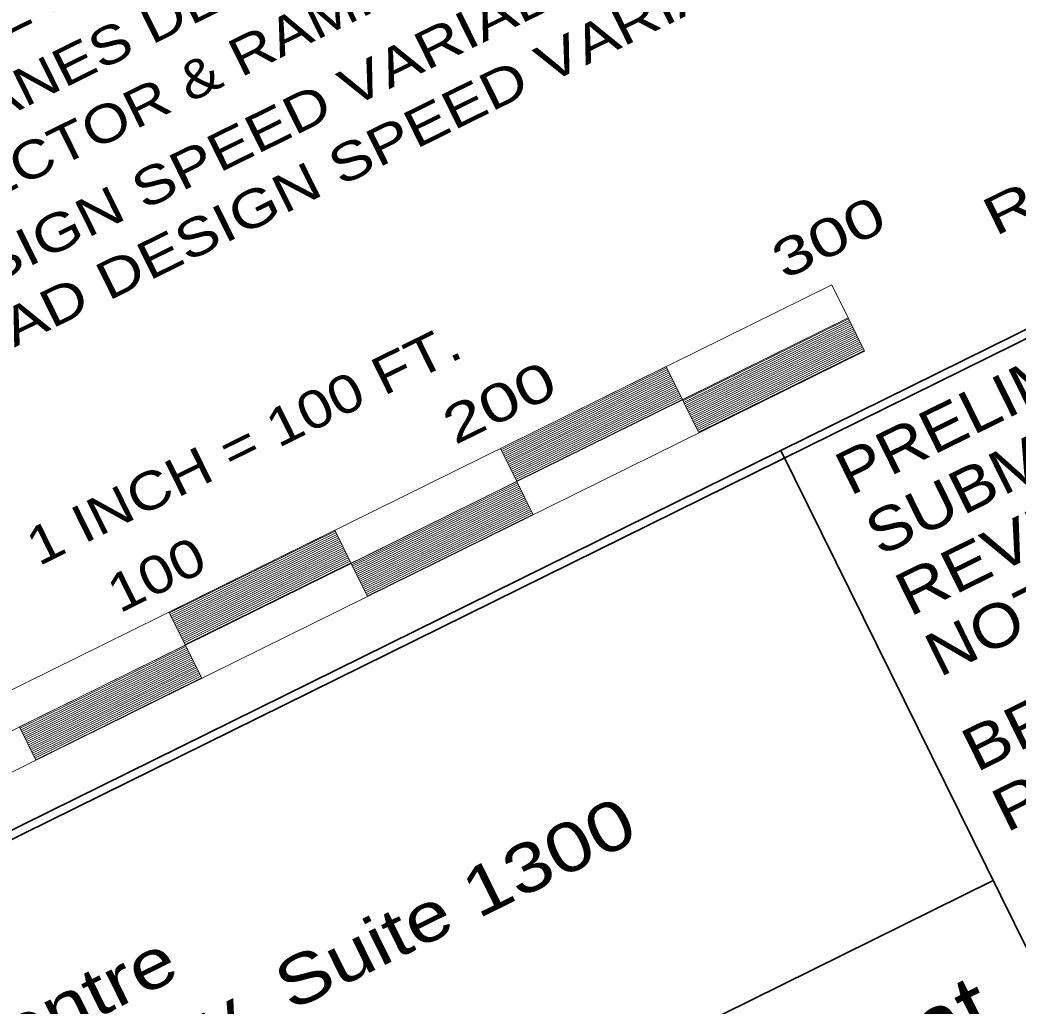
# Model space of a CAD drawing. Extents: x 2356606 to 2371222, y 6973096 to 6982644.
# Drawn here: x 2370337.8 to 2370607.9, y 6979398.7 to 6979665.5 of the extents above; entities that cross this region are included whole.
import ezdxf
from ezdxf.enums import TextEntityAlignment as Align

# ---------------------------------------------------------------- set-up
doc = ezdxf.new("R2010")
doc.units = 0
doc.header["$LTSCALE"] = 2
doc.layers.add('62', color=7, linetype='Continuous', lineweight=13)
doc.layers.add('63', color=7, linetype='Continuous', lineweight=13)

msp = doc.modelspace()

# ---------------------------------------------------------------- linework, layer by layer
at = {"layer": '62', "lineweight": 35}
for p, q in [((2370772.563, 6979661.979), (2370188.769, 6979373.856)), ((2370641.531, 6979350.877), (2370543.728, 6979549.041)), ((2370601.161, 6979432.671), (2370246.201, 6979257.487))]:
    msp.add_line(p, q, dxfattribs=at)
at = {"layer": '62'}
for p, q in [((2370198.776, 6979416.806), (2370557.503, 6979593.85)), ((2370557.503, 6979593.85), (2370561.929, 6979584.882)), ((2370203.203, 6979407.838), (2370561.929, 6979584.882)), ((2370517.206, 6979562.512), (2370562.047, 6979584.641)), ((2370517.428, 6979562.063), (2370562.268, 6979584.193)), ((2370517.648, 6979561.614), (2370562.49, 6979583.745)), ((2370517.869, 6979561.166), (2370562.711, 6979583.296)), ((2370518.09, 6979560.719), (2370562.932, 6979582.848)), ((2370561.929, 6979584.882), (2370566.356, 6979575.913)), ((2370518.312, 6979560.269), (2370563.153, 6979582.4)), ((2370518.533, 6979559.821), (2370563.374, 6979581.952)), ((2370518.755, 6979559.373), (2370563.596, 6979581.505)), ((2370518.977, 6979558.925), (2370563.817, 6979581.055)), ((2370519.198, 6979558.476), (2370564.038, 6979580.607)), ((2370519.419, 6979558.028), (2370564.261, 6979580.159)), ((2370519.641, 6979557.58), (2370564.482, 6979579.71)), ((2370519.86, 6979557.13), (2370564.703, 6979579.262)), ((2370520.082, 6979556.682), (2370564.923, 6979578.813)), ((2370520.304, 6979556.233), (2370565.145, 6979578.365)), ((2370520.525, 6979555.785), (2370565.366, 6979577.915)), ((2370520.747, 6979555.336), (2370565.588, 6979577.467)), ((2370520.968, 6979554.888), (2370565.81, 6979577.019)), ((2370521.19, 6979554.44), (2370566.03, 6979576.57)), ((2370521.411, 6979553.992), (2370566.253, 6979576.122)), ((2370512.661, 6979571.719), (2370517.087, 6979562.751)), ((2370467.995, 6979549.238), (2370512.834, 6979571.368)), ((2370468.217, 6979548.789), (2370513.057, 6979570.919)), ((2370468.438, 6979548.341), (2370513.277, 6979570.471)), ((2370468.658, 6979547.893), (2370513.499, 6979570.023)), ((2370468.879, 6979547.444), (2370513.72, 6979569.573)), ((2370469.101, 6979546.995), (2370513.941, 6979569.125)), ((2370469.323, 6979546.547), (2370514.163, 6979568.677)), ((2370469.543, 6979546.098), (2370514.384, 6979568.229)), ((2370469.765, 6979545.65), (2370514.605, 6979567.78)), ((2370469.987, 6979545.202), (2370514.827, 6979567.331)), ((2370470.207, 6979544.753), (2370515.049, 6979566.883)), ((2370470.429, 6979544.305), (2370515.27, 6979566.436)), ((2370470.65, 6979543.857), (2370515.49, 6979565.987)), ((2370470.872, 6979543.409), (2370515.711, 6979565.539)), ((2370471.092, 6979542.96), (2370515.933, 6979565.09)), ((2370471.314, 6979542.512), (2370516.155, 6979564.642)), ((2370471.536, 6979542.064), (2370516.376, 6979564.195)), ((2370471.756, 6979541.615), (2370516.597, 6979563.745)), ((2370471.978, 6979541.167), (2370516.819, 6979563.297)), ((2370472.2, 6979540.719), (2370517.039, 6979562.848)), ((2370517.087, 6979562.751), (2370521.514, 6979553.782)), ((2370467.822, 6979549.589), (2370472.248, 6979540.621)), ((2370427.579, 6979518.139), (2370472.419, 6979540.269)), ((2370427.801, 6979517.691), (2370472.641, 6979539.821)), ((2370428.021, 6979517.242), (2370472.863, 6979539.373)), ((2370472.248, 6979540.621), (2370476.673, 6979531.653)), ((2370428.243, 6979516.794), (2370473.085, 6979538.925)), ((2370428.465, 6979516.346), (2370473.305, 6979538.476)), ((2370428.685, 6979515.897), (2370473.526, 6979538.029)), ((2370428.907, 6979515.449), (2370473.748, 6979537.581)), ((2370429.128, 6979515.001), (2370473.969, 6979537.132)), ((2370429.349, 6979514.552), (2370474.191, 6979536.684)), ((2370429.571, 6979514.104), (2370474.412, 6979536.234)), ((2370429.792, 6979513.655), (2370474.633, 6979535.787)), ((2370430.014, 6979513.207), (2370474.855, 6979535.339)), ((2370430.235, 6979512.758), (2370475.076, 6979534.889)), ((2370430.457, 6979512.309), (2370475.298, 6979534.44)), ((2370430.677, 6979511.861), (2370475.519, 6979533.992)), ((2370430.899, 6979511.413), (2370475.74, 6979533.543)), ((2370431.12, 6979510.964), (2370475.961, 6979533.096)), ((2370431.341, 6979510.516), (2370476.182, 6979532.647)), ((2370431.563, 6979510.068), (2370476.405, 6979532.199)), ((2370431.784, 6979509.621), (2370476.625, 6979531.75)), ((2370378.269, 6979505.067), (2370423.108, 6979527.197)), ((2370378.49, 6979504.619), (2370423.33, 6979526.749)), ((2370378.712, 6979504.17), (2370423.552, 6979526.301)), ((2370378.933, 6979503.72), (2370423.773, 6979525.851)), ((2370422.981, 6979527.458), (2370427.406, 6979518.49)), ((2370379.154, 6979503.272), (2370423.995, 6979525.403)), ((2370379.375, 6979502.824), (2370424.215, 6979524.954)), ((2370379.596, 6979502.376), (2370424.437, 6979524.506)), ((2370379.818, 6979501.929), (2370424.657, 6979524.058)), ((2370380.039, 6979501.479), (2370424.879, 6979523.609)), ((2370380.261, 6979501.031), (2370425.101, 6979523.161)), ((2370380.482, 6979500.584), (2370425.322, 6979522.712)), ((2370380.702, 6979500.135), (2370425.544, 6979522.264)), ((2370380.924, 6979499.686), (2370425.765, 6979521.816)), ((2370381.145, 6979499.237), (2370425.986, 6979521.367)), ((2370381.367, 6979498.789), (2370426.208, 6979520.919)), ((2370381.588, 6979498.342), (2370426.428, 6979520.471)), ((2370381.809, 6979497.892), (2370426.649, 6979520.022)), ((2370382.031, 6979497.444), (2370426.871, 6979519.574)), ((2370382.252, 6979496.995), (2370427.092, 6979519.125)), ((2370382.474, 6979496.547), (2370427.314, 6979518.678)), ((2370427.406, 6979518.49), (2370431.832, 6979509.521)), ((2370378.139, 6979505.328), (2370382.566, 6979496.36)), ((2370382.566, 6979496.36), (2370386.992, 6979487.391)), ((2370337.896, 6979473.882), (2370382.737, 6979496.012)), ((2370338.117, 6979473.435), (2370382.958, 6979495.564)), ((2370338.338, 6979472.985), (2370383.18, 6979495.115)), ((2370338.559, 6979472.538), (2370383.401, 6979494.667)), ((2370338.781, 6979472.088), (2370383.623, 6979494.219)), ((2370339.002, 6979471.64), (2370383.845, 6979493.77)), ((2370339.223, 6979471.193), (2370384.064, 6979493.323)), ((2370339.445, 6979470.744), (2370384.286, 6979492.874)), ((2370339.667, 6979470.295), (2370384.507, 6979492.426)), ((2370339.887, 6979469.847), (2370384.729, 6979491.979)), ((2370340.109, 6979469.399), (2370384.951, 6979491.529)), ((2370340.329, 6979468.951), (2370385.171, 6979491.082)), ((2370340.551, 6979468.501), (2370385.392, 6979490.632)), ((2370340.773, 6979468.052), (2370385.613, 6979490.184)), ((2370340.994, 6979467.604), (2370385.836, 6979489.736)), ((2370341.215, 6979467.155), (2370386.056, 6979489.286)), ((2370341.437, 6979466.707), (2370386.277, 6979488.839)), ((2370341.659, 6979466.258), (2370386.499, 6979488.389)), ((2370341.88, 6979465.811), (2370386.72, 6979487.941)), ((2370342.101, 6979465.362), (2370386.943, 6979487.493)), ((2370337.726, 6979474.228), (2370342.15, 6979465.261))]:
    msp.add_line(p, q, dxfattribs=at)
for points in [[(2370521.514, 6979553.782), (2370566.356, 6979575.913), (2370561.929, 6979584.882), (2370517.087, 6979562.751)], [(2370472.248, 6979540.621), (2370517.087, 6979562.751), (2370512.661, 6979571.719), (2370467.822, 6979549.589)], [(2370431.832, 6979509.521), (2370476.673, 6979531.653), (2370472.248, 6979540.621), (2370427.406, 6979518.49)], [(2370382.566, 6979496.36), (2370427.406, 6979518.49), (2370422.981, 6979527.458), (2370378.139, 6979505.328)], [(2370342.15, 6979465.261), (2370386.992, 6979487.391), (2370382.566, 6979496.36), (2370337.726, 6979474.228)]]:
    msp.add_lwpolyline(points, close=True, dxfattribs=at)
at = {"layer": '63', "lineweight": 35}
msp.add_line((2370771.897, 6979659.152), (2370188.104, 6979371.029), dxfattribs=at)
at = {"layer": '63'}
for p, q in [((2370198.776, 6979416.806), (2370557.503, 6979593.85)), ((2370557.503, 6979593.85), (2370561.929, 6979584.882)), ((2370203.203, 6979407.838), (2370561.929, 6979584.882)), ((2370517.206, 6979562.512), (2370562.047, 6979584.641)), ((2370517.428, 6979562.063), (2370562.268, 6979584.193)), ((2370517.648, 6979561.614), (2370562.49, 6979583.745)), ((2370517.869, 6979561.166), (2370562.711, 6979583.296)), ((2370518.09, 6979560.719), (2370562.932, 6979582.848)), ((2370561.929, 6979584.882), (2370566.356, 6979575.913)), ((2370518.312, 6979560.269), (2370563.153, 6979582.4)), ((2370518.533, 6979559.821), (2370563.374, 6979581.952)), ((2370518.755, 6979559.373), (2370563.596, 6979581.505)), ((2370518.977, 6979558.925), (2370563.817, 6979581.055)), ((2370519.198, 6979558.476), (2370564.038, 6979580.607)), ((2370519.419, 6979558.028), (2370564.261, 6979580.159)), ((2370519.641, 6979557.58), (2370564.482, 6979579.71)), ((2370519.86, 6979557.13), (2370564.703, 6979579.262)), ((2370520.082, 6979556.682), (2370564.923, 6979578.813)), ((2370520.304, 6979556.233), (2370565.145, 6979578.365)), ((2370520.525, 6979555.785), (2370565.366, 6979577.915)), ((2370520.747, 6979555.336), (2370565.588, 6979577.467)), ((2370207.628, 6979398.87), (2370566.356, 6979575.913)), ((2370520.968, 6979554.888), (2370565.81, 6979577.019)), ((2370521.19, 6979554.44), (2370566.03, 6979576.57)), ((2370521.411, 6979553.992), (2370566.253, 6979576.122)), ((2370512.661, 6979571.719), (2370517.087, 6979562.751)), ((2370467.995, 6979549.238), (2370512.834, 6979571.368)), ((2370468.217, 6979548.789), (2370513.057, 6979570.919)), ((2370468.438, 6979548.341), (2370513.277, 6979570.471)), ((2370468.658, 6979547.893), (2370513.499, 6979570.023)), ((2370468.879, 6979547.444), (2370513.72, 6979569.573)), ((2370469.101, 6979546.995), (2370513.941, 6979569.125)), ((2370469.323, 6979546.547), (2370514.163, 6979568.677)), ((2370469.543, 6979546.098), (2370514.384, 6979568.229)), ((2370469.765, 6979545.65), (2370514.605, 6979567.78)), ((2370469.987, 6979545.202), (2370514.827, 6979567.331)), ((2370470.207, 6979544.753), (2370515.049, 6979566.883)), ((2370470.429, 6979544.305), (2370515.27, 6979566.436)), ((2370470.65, 6979543.857), (2370515.49, 6979565.987)), ((2370470.872, 6979543.409), (2370515.711, 6979565.539)), ((2370471.092, 6979542.96), (2370515.933, 6979565.09)), ((2370471.314, 6979542.512), (2370516.155, 6979564.642)), ((2370471.536, 6979542.064), (2370516.376, 6979564.195)), ((2370471.756, 6979541.615), (2370516.597, 6979563.745)), ((2370471.978, 6979541.167), (2370516.819, 6979563.297)), ((2370472.2, 6979540.719), (2370517.039, 6979562.848)), ((2370517.087, 6979562.751), (2370521.514, 6979553.782)), ((2370467.822, 6979549.589), (2370472.248, 6979540.621)), ((2370427.579, 6979518.139), (2370472.419, 6979540.269)), ((2370427.801, 6979517.691), (2370472.641, 6979539.821)), ((2370428.021, 6979517.242), (2370472.863, 6979539.373)), ((2370472.248, 6979540.621), (2370476.673, 6979531.653)), ((2370428.243, 6979516.794), (2370473.085, 6979538.925)), ((2370428.465, 6979516.346), (2370473.305, 6979538.476)), ((2370428.685, 6979515.897), (2370473.526, 6979538.029)), ((2370428.907, 6979515.449), (2370473.748, 6979537.581)), ((2370429.128, 6979515.001), (2370473.969, 6979537.132)), ((2370429.349, 6979514.552), (2370474.191, 6979536.684)), ((2370429.571, 6979514.104), (2370474.412, 6979536.234)), ((2370429.792, 6979513.655), (2370474.633, 6979535.787)), ((2370430.014, 6979513.207), (2370474.855, 6979535.339)), ((2370430.235, 6979512.758), (2370475.076, 6979534.889)), ((2370430.457, 6979512.309), (2370475.298, 6979534.44)), ((2370430.677, 6979511.861), (2370475.519, 6979533.992)), ((2370430.899, 6979511.413), (2370475.74, 6979533.543)), ((2370431.12, 6979510.964), (2370475.961, 6979533.096)), ((2370431.341, 6979510.516), (2370476.182, 6979532.647)), ((2370431.563, 6979510.068), (2370476.405, 6979532.199)), ((2370431.784, 6979509.621), (2370476.625, 6979531.75)), ((2370378.269, 6979505.067), (2370423.108, 6979527.197)), ((2370378.49, 6979504.619), (2370423.33, 6979526.749)), ((2370378.712, 6979504.17), (2370423.552, 6979526.301)), ((2370378.933, 6979503.72), (2370423.773, 6979525.851)), ((2370422.981, 6979527.458), (2370427.406, 6979518.49)), ((2370379.154, 6979503.272), (2370423.995, 6979525.403)), ((2370379.375, 6979502.824), (2370424.215, 6979524.954)), ((2370379.596, 6979502.376), (2370424.437, 6979524.506)), ((2370379.818, 6979501.929), (2370424.657, 6979524.058)), ((2370380.039, 6979501.479), (2370424.879, 6979523.609)), ((2370380.261, 6979501.031), (2370425.101, 6979523.161)), ((2370380.482, 6979500.584), (2370425.322, 6979522.712)), ((2370380.702, 6979500.135), (2370425.544, 6979522.264)), ((2370380.924, 6979499.686), (2370425.765, 6979521.816)), ((2370381.145, 6979499.237), (2370425.986, 6979521.367)), ((2370381.367, 6979498.789), (2370426.208, 6979520.919)), ((2370381.588, 6979498.342), (2370426.428, 6979520.471)), ((2370381.809, 6979497.892), (2370426.649, 6979520.022)), ((2370382.031, 6979497.444), (2370426.871, 6979519.574)), ((2370382.252, 6979496.995), (2370427.092, 6979519.125)), ((2370382.474, 6979496.547), (2370427.314, 6979518.678)), ((2370427.406, 6979518.49), (2370431.832, 6979509.521)), ((2370378.139, 6979505.328), (2370382.566, 6979496.36)), ((2370382.566, 6979496.36), (2370386.992, 6979487.391)), ((2370337.896, 6979473.882), (2370382.737, 6979496.012)), ((2370338.117, 6979473.435), (2370382.958, 6979495.564)), ((2370338.338, 6979472.985), (2370383.18, 6979495.115)), ((2370338.559, 6979472.538), (2370383.401, 6979494.667)), ((2370338.781, 6979472.088), (2370383.623, 6979494.219)), ((2370339.002, 6979471.64), (2370383.845, 6979493.77)), ((2370339.223, 6979471.193), (2370384.064, 6979493.323)), ((2370339.445, 6979470.744), (2370384.286, 6979492.874)), ((2370339.667, 6979470.295), (2370384.507, 6979492.426)), ((2370339.887, 6979469.847), (2370384.729, 6979491.979)), ((2370340.109, 6979469.399), (2370384.951, 6979491.529)), ((2370340.329, 6979468.951), (2370385.171, 6979491.082)), ((2370340.551, 6979468.501), (2370385.392, 6979490.632)), ((2370340.773, 6979468.052), (2370385.613, 6979490.184)), ((2370340.994, 6979467.604), (2370385.836, 6979489.736)), ((2370341.215, 6979467.155), (2370386.056, 6979489.286)), ((2370341.437, 6979466.707), (2370386.277, 6979488.839)), ((2370341.659, 6979466.258), (2370386.499, 6979488.389)), ((2370341.88, 6979465.811), (2370386.72, 6979487.941)), ((2370342.101, 6979465.362), (2370386.943, 6979487.493)), ((2370337.726, 6979474.228), (2370342.15, 6979465.261))]:
    msp.add_line(p, q, dxfattribs=at)
for points in [[(2370521.514, 6979553.782), (2370566.356, 6979575.913), (2370561.929, 6979584.882), (2370517.087, 6979562.751)], [(2370472.248, 6979540.621), (2370517.087, 6979562.751), (2370512.661, 6979571.719), (2370467.822, 6979549.589)], [(2370431.832, 6979509.521), (2370476.673, 6979531.653), (2370472.248, 6979540.621), (2370427.406, 6979518.49)], [(2370382.566, 6979496.36), (2370427.406, 6979518.49), (2370422.981, 6979527.458), (2370378.139, 6979505.328)], [(2370342.15, 6979465.261), (2370386.992, 6979487.391), (2370382.566, 6979496.36), (2370337.726, 6979474.228)]]:
    msp.add_lwpolyline(points, close=True, dxfattribs=at)

# ---------------------------------------------------------------- texts
at = {"layer": '62'}
for s, height, width, p in [('DIRECT CONNECTOR & RAMP DESIGN SPEED = 50 MPH', 10.2, 1.2, (2370425.126, 6979663.505)), ('MAIN LANES DESIGN SPEED = 60 MPH', 10.2, 1.2, (2370416.906, 6979680.165)), ('FRONTAGE ROAD DESIGN SPEED VARIABLE 35 TO 40 MPH', 10.2, 1.25, (2370442.894, 6979629.485)), ('RAMP DESIGN SPEED VARIABLE 40 TO 50 MPH', 10.2, 1.25, (2370434.232, 6979645.054)), ('ROLL 3 OF 4', 10.2, 1.4, (2370652.643, 6979632.005)), ('300', 10.2, 1.4, (2370558.899, 6979602.167)), ('SCALE:  1 INCH = 100 FT.', 10.2, 1.2, (2370370.377, 6979531.207)), ('200', 10.2, 1.4, (2370469.795, 6979557.467)), ('100', 10.2, 1.2, (2370376.975, 6979510.919)), ('Texas Department', 18.76, 1.1, (2370501.79, 6979340.989))]:
    msp.add_text(s, height=height, rotation=26.268, dxfattribs=dict(at, width=width)).set_placement(p, align=Align.CENTER)
for s, height, width, p in [('CONTROL NO.  0008-13-123, 124, 138', 10.2, 1.2, (2370269.924, 6979629.556)), ('PRELIMINARY PLAN', 11.74, 1.15, (2370562.428, 6979536.614)), ('NOT FOR CONSTRUCTION.', 11.74, 1.15, (2370586.649, 6979487.539)), ('SUBMITTAL FOR', 11.74, 1.15, (2370570.502, 6979520.256)), ('REVIEW ONLY', 11.74, 1.2, (2370578.575, 6979503.898)), ('BRENT R. KYLER', 11.74, 1.2, (2370596.614, 6979461.832)), ('PE NO. 77841', 11.74, 1.25, (2370604.685, 6979445.478)), ('3010 LBJ Freeway, Suite 1300', 13.22, 1.25, (2370234.848, 6979310.249)), ('Graystone Centre', 13.22, 1.25, (2370225.312, 6979329.572))]:
    msp.add_text(s, height=height, rotation=26.268, dxfattribs=dict(at, width=width)).set_placement(p)
at = {"layer": '63'}
for s, height, width, p in [('DIRECT CONNECTOR & RAMP DESIGN SPEED = 50 MPH', 10.2, 1.2, (2370425.126, 6979663.505)), ('MAIN LANES DESIGN SPEED = 60 MPH', 10.2, 1.2, (2370416.906, 6979680.165)), ('300', 10.2, 1.4, (2370558.899, 6979602.167)), ('200', 10.2, 1.4, (2370469.795, 6979557.467)), ('100', 10.2, 1.2, (2370376.975, 6979510.919)), ('Texas Department', 18.76, 1.1, (2370501.79, 6979340.989))]:
    msp.add_text(s, height=height, rotation=26.268, dxfattribs=dict(at, width=width)).set_placement(p, align=Align.CENTER)

doc.saveas('drawing.dxf')
